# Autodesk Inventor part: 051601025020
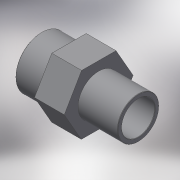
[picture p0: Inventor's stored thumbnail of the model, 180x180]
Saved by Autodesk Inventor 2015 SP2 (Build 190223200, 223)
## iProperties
Created: 2017-10
Part Number: 051601025020
Material: Generic
Description: PLASSON THR. REDUCING NIPPLE 2"-2.1/2" PVC
Document SubType Name: Modeling
Designer: KIM
Density: 1 g/cm^3
Appearance: Default
Author: KIM
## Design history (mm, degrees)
derived "051601.ipt"
feature "Solid1::051601.ipt"
tag "TaggingFeature1"
body "Solid1"
other parameters: "d0" = 76, "d13" = 0, "d14" = 0.59614, "d17" = 26, "d18" = 36, "d19" = 75.184, "d21" = 59.614, "d23" = 60.1472, "d24" = 47.6912, "d26" = -26, "R_1" = 59.614, "lt_1" = 26, "H_" = 76, "R_" = 75.184
